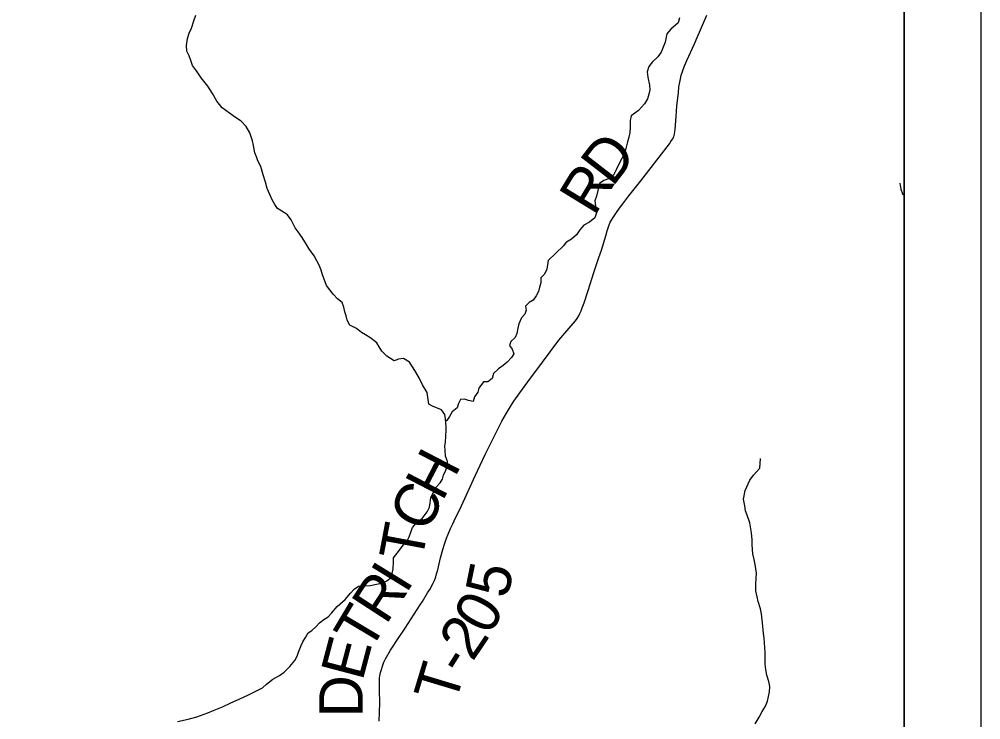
# Model space of a CAD drawing. Extents: x -7.1 to 34, y 0 to 22.
# Drawn here: x 7.746 to 9, y 16.733 to 17.646 of the extents above; entities that cross this region are included whole.
import ezdxf

# ---------------------------------------------------------------- set-up
doc = ezdxf.new("R2010")
doc.units = 0
for name, color, linetype in [('GM_X_Minor_River', 7, 'Continuous'), ('GM_X_Township_Road', 7, 'Continuous'), ('GM_X_Township_Road_Text', 7, 'Continuous'), ('SH_Cut_Line', 7, 'Continuous'), ('SH_Data', 7, 'Continuous')]:
    doc.layers.add(name, color=color, linetype=linetype)

msp = doc.modelspace()

# ---------------------------------------------------------------- linework, layer by layer
at = {"layer": 'GM_X_Minor_River'}
for points in [[(8.0963, 17.3907), (8.091, 17.3944), (8.083, 17.3988), (8.0795, 17.4041), (8.076, 17.4101), (8.0729, 17.4173), (8.0694, 17.4249), (8.0674, 17.4332), (8.0646, 17.4427), (8.0614, 17.4537), (8.0575, 17.4613), (8.0555, 17.4662), (8.0536, 17.4715), (8.0519, 17.481), (8.0503, 17.4871), (8.0468, 17.4977), (8.0421, 17.506), (8.0359, 17.5128), (8.0283, 17.5176), (8.0203, 17.5232), (8.0111, 17.5303), (8.0041, 17.5389), (7.9983, 17.5491), (7.9921, 17.5586), (7.9836, 17.5695), (7.9775, 17.5785), (7.9724, 17.5853), (7.9701, 17.5918), (7.9677, 17.5978), (7.965, 17.6039), (7.9645, 17.6115), (7.9659, 17.6206), (7.9681, 17.6275), (7.971, 17.6341), (7.9739, 17.6436), (7.9764, 17.6509)], [(8.6072, 17.6474), (8.6056, 17.6409), (8.5957, 17.6326), (8.5908, 17.6269), (8.5884, 17.6159), (8.5857, 17.6094), (8.5831, 17.6026), (8.5789, 17.5965), (8.572, 17.5901), (8.5674, 17.584), (8.5651, 17.5772), (8.5658, 17.5703), (8.5681, 17.5597), (8.5684, 17.5536), (8.5672, 17.5479), (8.5653, 17.5418), (8.5615, 17.5354), (8.5539, 17.5266), (8.5443, 17.5198), (8.5428, 17.5137), (8.5431, 17.5046), (8.5423, 17.4982), (8.5412, 17.4921), (8.5396, 17.486), (8.5373, 17.4773), (8.535, 17.4697), (8.5281, 17.4568), (8.5246, 17.4492), (8.5212, 17.4423), (8.5147, 17.4378), (8.5086, 17.4355), (8.5029, 17.4314), (8.5006, 17.4226), (8.4991, 17.415), (8.4968, 17.4089), (8.4982, 17.3991), (8.499, 17.3934), (8.497, 17.3869), (8.4898, 17.3812), (8.4826, 17.3771), (8.4772, 17.3714), (8.473, 17.3645), (8.4665, 17.3592), (8.4597, 17.3551), (8.4596, 17.3548)], [(8.8945, 17.4319), (8.8956, 17.4242), (8.8979, 17.4182), (8.9, 17.4164)], [(8.1087, 16.8155), (8.1106, 16.8208), (8.1138, 16.8293), (8.116, 16.8342), (8.1194, 16.84), (8.1231, 16.8458), (8.128, 16.8489), (8.1332, 16.8539), (8.138, 16.8589), (8.1436, 16.8632), (8.1493, 16.8667), (8.1534, 16.8717), (8.1608, 16.8802), (8.1713, 16.8895), (8.1784, 16.8976), (8.1832, 16.9027), (8.1888, 16.9065), (8.1941, 16.907), (8.204, 16.9075), (8.2145, 16.9096), (8.2206, 16.9112), (8.2258, 16.9136), (8.2311, 16.9182), (8.2325, 16.9232), (8.2339, 16.9293), (8.2342, 16.9381), (8.2341, 16.9438), (8.2423, 16.9538), (8.2471, 16.96), (8.252, 16.9658), (8.2549, 16.9711), (8.2571, 16.9769), (8.2593, 16.983), (8.2638, 16.9888), (8.2716, 16.995), (8.2783, 17.0035), (8.2813, 17.0096), (8.2823, 17.0153), (8.283, 17.0222), (8.287, 17.0295), (8.2896, 17.0353), (8.2952, 17.0414), (8.2981, 17.0464), (8.2996, 17.0514), (8.3025, 17.0579), (8.3043, 17.0637), (8.3046, 17.0694), (8.3019, 17.0762), (8.3018, 17.0842), (8.3013, 17.0891), (8.302, 17.0945), (8.3029, 17.1101), (8.3028, 17.115), (8.3023, 17.1249), (8.3011, 17.1306), (8.2968, 17.1366), (8.2919, 17.1389), (8.2862, 17.1407), (8.2805, 17.144), (8.2792, 17.1531), (8.278, 17.1592), (8.2722, 17.169), (8.2683, 17.1773), (8.2636, 17.1856), (8.2601, 17.1913), (8.2551, 17.1988), (8.2474, 17.2037), (8.241, 17.2024), (8.235, 17.2004), (8.2258, 17.2064), (8.2193, 17.2131), (8.2158, 17.2188), (8.2127, 17.2241), (8.2035, 17.2308), (8.1978, 17.2345), (8.1924, 17.2375), (8.1859, 17.2427), (8.1775, 17.2468), (8.174, 17.2536), (8.1724, 17.2593), (8.1708, 17.2642), (8.1696, 17.2703), (8.1673, 17.2763), (8.1615, 17.2812), (8.1557, 17.2872), (8.1511, 17.2932), (8.1469, 17.2985), (8.1453, 17.3034), (8.1418, 17.3125), (8.1398, 17.3186), (8.1374, 17.325), (8.1343, 17.3307), (8.1308, 17.3375), (8.1239, 17.3469), (8.1211, 17.3522), (8.1153, 17.3612), (8.1099, 17.3684), (8.1061, 17.3737), (8.1037, 17.379), (8.101, 17.3842), (8.0963, 17.3907)], [(8.4593, 17.355), (8.456, 17.3502), (8.4361, 17.3311), (8.435, 17.3254), (8.4343, 17.32), (8.431, 17.3135), (8.4262, 17.3088), (8.4263, 17.302), (8.4248, 17.2966), (8.4234, 17.2909), (8.4204, 17.2852), (8.4164, 17.2794), (8.4111, 17.2766), (8.4066, 17.2716), (8.4075, 17.2663), (8.4056, 17.2613), (8.4012, 17.2563), (8.3979, 17.2486), (8.3964, 17.2429), (8.395, 17.236), (8.3928, 17.231), (8.3872, 17.2256), (8.3854, 17.2206), (8.3892, 17.2157), (8.3912, 17.2097), (8.3883, 17.2047), (8.3827, 17.1985), (8.3771, 17.1942), (8.3711, 17.19), (8.3647, 17.1838), (8.3629, 17.1773), (8.3573, 17.173), (8.3516, 17.1729), (8.3457, 17.1648), (8.3442, 17.1595), (8.3398, 17.1533), (8.3383, 17.1476), (8.3319, 17.1486), (8.3269, 17.1504), (8.3216, 17.15), (8.3191, 17.145), (8.3173, 17.1392), (8.3109, 17.1338), (8.3072, 17.128), (8.3039, 17.1227), (8.3025, 17.1217)], [(8.7058, 16.7273), (8.7111, 16.736), (8.7149, 16.7432), (8.7192, 16.7504), (8.7218, 16.7569), (8.7245, 16.769), (8.725, 16.7759), (8.7238, 16.7823), (8.7212, 16.7907), (8.7197, 16.7983), (8.719, 16.8052), (8.7187, 16.8132), (8.7187, 16.8196), (8.7184, 16.8268), (8.7176, 16.839), (8.7169, 16.8451), (8.7155, 16.8588), (8.714, 16.8706), (8.7129, 16.877), (8.7099, 16.8869), (8.7084, 16.893), (8.7069, 16.9006), (8.7066, 16.9094), (8.707, 16.917), (8.7074, 16.9238), (8.7059, 16.9348), (8.7044, 16.9413), (8.7026, 16.9489), (8.7022, 16.9546), (8.7019, 16.9611), (8.7019, 16.9672), (8.7012, 16.9763), (8.699, 16.9892), (8.6956, 16.9991), (8.6933, 17.0048), (8.6922, 17.0113), (8.6908, 17.02), (8.6927, 17.0314), (8.6988, 17.0447), (8.7038, 17.0512), (8.7118, 17.0606), (8.7126, 17.0732)], [(7.9528, 16.7301), (7.9664, 16.7333), (7.9781, 16.7366), (7.9921, 16.7414), (8.0003, 16.7449), (8.0113, 16.7496), (8.0222, 16.7548), (8.0331, 16.7595), (8.0451, 16.765), (8.0541, 16.7693), (8.0635, 16.774), (8.0688, 16.7791), (8.077, 16.7857), (8.0856, 16.7904), (8.0916, 16.7947), (8.0991, 16.802), (8.1058, 16.8097), (8.1087, 16.8155)]]:
    msp.add_lwpolyline(points, dxfattribs=at)
at = {"layer": 'GM_X_Township_Road'}
msp.add_lwpolyline([(6.633, 14.1), (8.9, 14.1), (8.9, 17.7079), (8.6668, 17.7136), (8.4472, 17.7189), (7.7202, 17.7285), (6.7118, 17.7486), (6.7058, 17.2839), (6.6822, 16.3488), (6.6748, 15.9993), (6.6586, 15.2372), (6.6565, 15.1357)], close=True, dxfattribs=at)
msp.add_lwpolyline([(8.2156, 16.7307), (8.216, 16.7421), (8.2163, 16.7552), (8.216, 16.7709), (8.2159, 16.7798), (8.216, 16.7846), (8.2162, 16.7874), (8.2164, 16.7899), (8.2173, 16.794), (8.2185, 16.7981), (8.2201, 16.8025), (8.2219, 16.8075), (8.224, 16.812), (8.2302, 16.8231), (8.2339, 16.8286), (8.2379, 16.8347), (8.2494, 16.8521), (8.2693, 16.8822), (8.2722, 16.8867), (8.2788, 16.8979), (8.2818, 16.9025), (8.2859, 16.9108), (8.2877, 16.9141), (8.2894, 16.9188), (8.2905, 16.9226), (8.292, 16.9279), (8.2957, 16.9435), (8.2987, 16.9547), (8.3006, 16.9616), (8.3034, 16.9693), (8.3054, 16.9743), (8.3086, 16.9817), (8.3116, 16.9879), (8.3135, 16.9917), (8.3229, 17.0116), (8.3408, 17.0505), (8.354, 17.0784), (8.3633, 17.0976), (8.3725, 17.1158), (8.3757, 17.1219), (8.3815, 17.1323), (8.3868, 17.1409), (8.3914, 17.148), (8.3989, 17.1586), (8.4093, 17.173), (8.4284, 17.1988), (8.4497, 17.2275), (8.4575, 17.2366), (8.4717, 17.2525), (8.4738, 17.2556), (8.4759, 17.2591), (8.4774, 17.2621), (8.4789, 17.2657), (8.4805, 17.2696), (8.4828, 17.2762), (8.4883, 17.292), (8.4957, 17.3157), (8.5022, 17.3351), (8.5053, 17.3447), (8.511, 17.3633), (8.5129, 17.3699), (8.5149, 17.3766), (8.517, 17.381), (8.5223, 17.3899), (8.5258, 17.395), (8.5303, 17.4011), (8.5333, 17.405), (8.5413, 17.4155), (8.5567, 17.4351), (8.5672, 17.4487), (8.5941, 17.4833), (8.5961, 17.4862), (8.5981, 17.4893), (8.5997, 17.4926), (8.6008, 17.4961), (8.6012, 17.4993), (8.6016, 17.5022), (8.6029, 17.5188), (8.6039, 17.5327), (8.6058, 17.5498), (8.6065, 17.5576), (8.6077, 17.5637), (8.6083, 17.5681), (8.6092, 17.5729), (8.6105, 17.5765), (8.612, 17.5802), (8.6143, 17.5858), (8.6169, 17.5918), (8.6268, 17.6136), (8.6303, 17.6219), (8.6346, 17.6319), (8.643, 17.6511)], dxfattribs=at)
at = {"layer": 'SH_Cut_Line'}
msp.add_lwpolyline([(2.1, 17.7253), (2.1, 14.1), (8.9, 14.1), (8.9, 17.7079), (8.6668, 17.7136), (8.4472, 17.7189), (7.7202, 17.7285), (6.7118, 17.7486), (6.3575, 17.7557), (6.1904, 17.7592), (5.7514, 17.7685), (5.5047, 17.7737), (5.1115, 17.7819), (5.0544, 17.7831), (5.0443, 17.7832), (4.7094, 17.7848), (4.5657, 17.7857), (4.3, 17.7873), (3.8304, 17.7952), (3.8238, 17.6717), (3.7215, 17.6707), (3.0659, 17.6986), (2.7886, 17.7105), (2.5551, 17.7155)], close=True, dxfattribs=at)
at = {"layer": 'SH_Data'}
for p, q in [((9, 21), (9, 14)), ((8.9, 20.9), (8.9, 14.1))]:
    msp.add_line(p, q, dxfattribs=at)

# ---------------------------------------------------------------- texts
at = {"layer": 'GM_X_Township_Road_Text'}
for s, rotation, p in [('D', 52.3017, (8.5197, 17.426)), ('R', 58.5556, (8.4962, 17.3875)), ('H', 62.5633, (8.298, 17.016)), ('C', 64.0371, (8.2777, 16.9744)), ('T', 79.3161, (8.2711, 16.9365)), ('I', 58.4119, (8.2508, 16.8956)), ('5', 78.6219, (8.3831, 16.8893)), ('R', 56.9702, (8.2245, 16.8551)), ('0', 61.0799, (8.3596, 16.8409)), ('T', 59.2185, (8.2031, 16.8191)), ('2', 56.0718, (8.3373, 16.8073)), ('E', 75.2185, (8.1938, 16.7819)), ('-', 57.8862, (8.3251, 16.7879)), ('T', 73.2187, (8.3145, 16.7509)), ('D', 89.8907, (8.1942, 16.7357))]:
    msp.add_text(s, height=0.0568, rotation=rotation, dxfattribs=at).set_placement(p)

doc.saveas('drawing.dxf')
